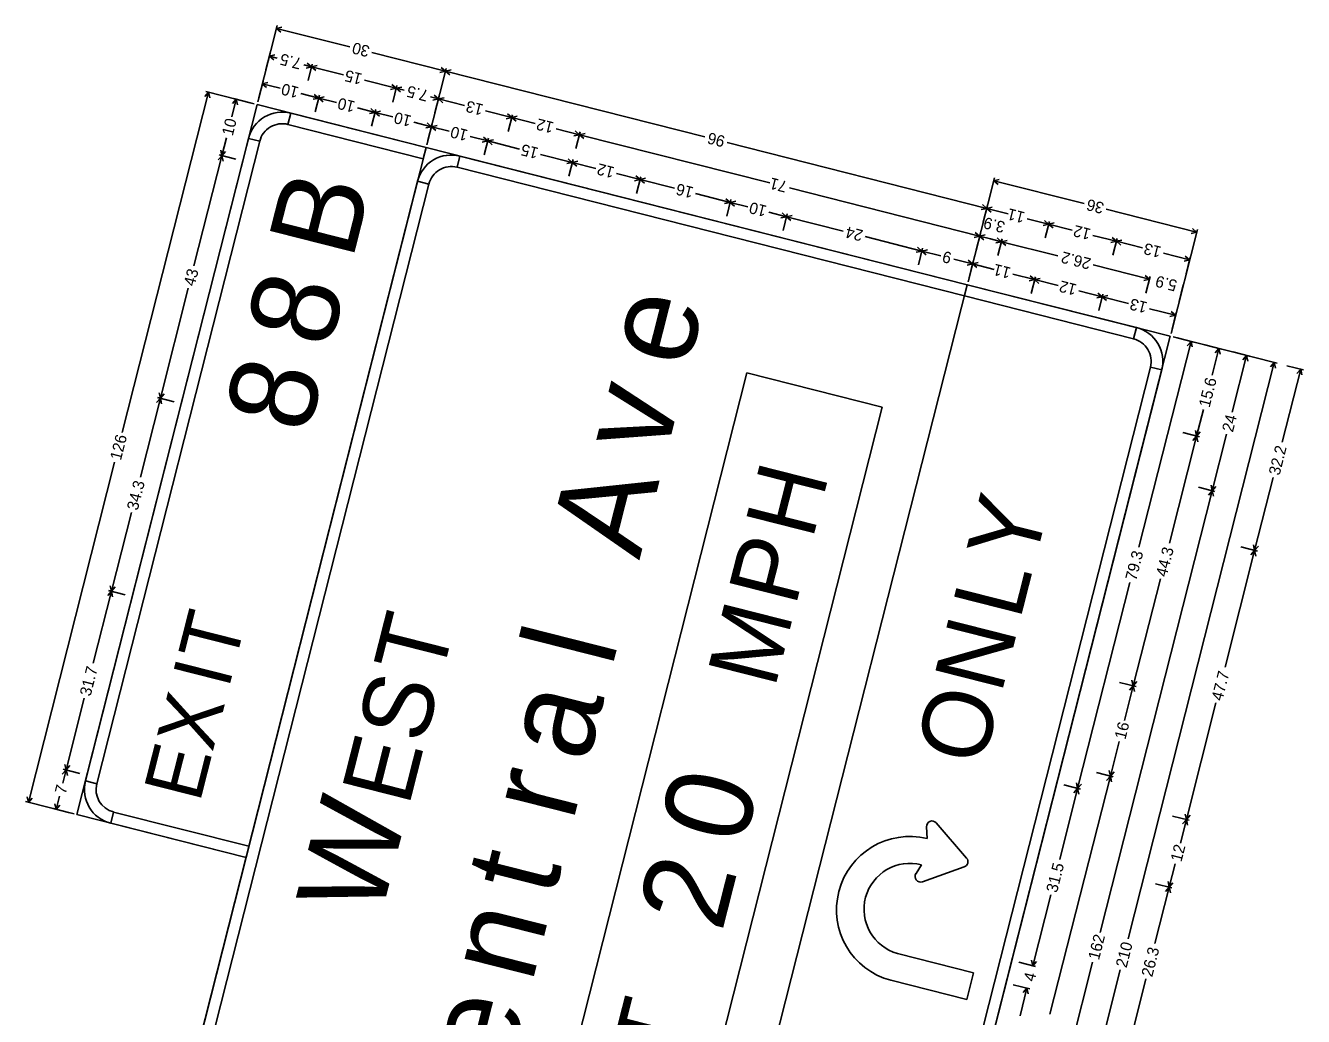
# Model space of a CAD drawing. Extents: x 670003 to 670131, y 737764 to 738002.
# Drawn here: x 670009.58 to 670027.92, y 737772.13 to 737786.35 of the extents above; entities that cross this region are included whole.
import ezdxf

# ---------------------------------------------------------------- set-up
doc = ezdxf.new("R2010")
doc.units = 0
doc.layers.add('R_SIGN', color=7, linetype='Continuous')

msp = doc.modelspace()

# ---------------------------------------------------------------- linework, layer by layer
at = {"layer": 'R_SIGN'}
for p, q in [((670013.193, 737786.345), (670012.915, 737785.251)), ((670013.263, 737786.323), (670013.183, 737786.305)), ((670014.238, 737786.038), (670013.183, 737786.305)), ((670013.245, 737786.252), (670013.183, 737786.305)), ((670013.092, 737785.947), (670013.031, 737785.708)), ((670013.162, 737785.925), (670013.082, 737785.907)), ((670013.195, 737785.879), (670013.082, 737785.907)), ((670013.144, 737785.854), (670013.082, 737785.907)), ((670014.553, 737785.958), (670015.609, 737785.69)), ((670013.575, 737785.782), (670013.688, 737785.754)), ((670013.608, 737785.736), (670013.688, 737785.754)), ((670013.626, 737785.807), (670013.688, 737785.754)), ((670013.698, 737785.793), (670013.638, 737785.555)), ((670013.768, 737785.771), (670013.688, 737785.754)), ((670014.144, 737785.638), (670013.688, 737785.754)), ((670013.75, 737785.7), (670013.688, 737785.754)), ((670015.619, 737785.73), (670015.341, 737784.635)), ((670015.619, 737785.73), (670015.341, 737784.635)), ((670015.528, 737785.672), (670015.609, 737785.69)), ((670015.547, 737785.744), (670015.609, 737785.69)), ((670015.689, 737785.708), (670015.609, 737785.69)), ((670019.331, 737784.746), (670015.609, 737785.69)), ((670015.671, 737785.636), (670015.609, 737785.69)), ((670012.991, 737785.549), (670012.93, 737785.31)), ((670013.061, 737785.527), (670012.981, 737785.509)), ((670013.235, 737785.445), (670012.981, 737785.509)), ((670013.043, 737785.456), (670012.981, 737785.509)), ((670014.445, 737785.562), (670014.901, 737785.446)), ((670014.839, 737785.5), (670014.901, 737785.446)), ((670010.971, 737780.508), (670012.209, 737785.388)), ((670012.155, 737785.325), (670012.209, 737785.388)), ((670012.169, 737785.398), (670012.865, 737785.221)), ((670012.226, 737785.307), (670012.209, 737785.388)), ((670013.535, 737785.369), (670013.79, 737785.304)), ((670013.727, 737785.358), (670013.79, 737785.304)), ((670013.8, 737785.344), (670013.739, 737785.105)), ((670013.87, 737785.322), (670013.79, 737785.304)), ((670014.821, 737785.428), (670014.901, 737785.446)), ((670014.911, 737785.486), (670014.851, 737785.247)), ((670014.911, 737785.486), (670014.851, 737785.247)), ((670014.981, 737785.463), (670014.901, 737785.446)), ((670015.015, 737785.417), (670014.901, 737785.446)), ((670014.963, 737785.392), (670014.901, 737785.446)), ((670015.394, 737785.321), (670015.508, 737785.292)), ((670015.446, 737785.346), (670015.508, 737785.292)), ((670015.518, 737785.332), (670015.457, 737785.093)), ((670015.518, 737785.332), (670015.457, 737785.093)), ((670015.588, 737785.31), (670015.508, 737785.292)), ((670012.905, 737785.211), (670010.321, 737775.022)), ((670012.542, 737785.033), (670012.607, 737785.287)), ((670012.553, 737785.225), (670012.607, 737785.287)), ((670012.567, 737785.297), (670012.806, 737785.236)), ((670012.624, 737785.206), (670012.607, 737785.287)), ((670015.331, 737784.596), (670012.905, 737785.211)), ((670013.709, 737785.287), (670013.79, 737785.304)), ((670014.044, 737785.24), (670013.79, 737785.304)), ((670013.852, 737785.251), (670013.79, 737785.304)), ((670014.344, 737785.164), (670014.598, 737785.099)), ((670014.536, 737785.153), (670014.598, 737785.099)), ((670014.608, 737785.139), (670014.548, 737784.9)), ((670014.608, 737785.139), (670014.548, 737784.9)), ((670015.428, 737785.275), (670015.508, 737785.292)), ((670015.883, 737785.197), (670015.508, 737785.292)), ((670015.57, 737785.238), (670015.508, 737785.292)), ((670013.349, 737784.926), (670013.39, 737785.088)), ((670014.518, 737785.082), (670014.598, 737785.099)), ((670014.678, 737785.117), (670014.598, 737785.099)), ((670014.852, 737785.035), (670014.598, 737785.099)), ((670014.66, 737785.046), (670014.598, 737785.099)), ((670015.153, 737784.959), (670015.407, 737784.894)), ((670015.345, 737784.948), (670015.407, 737784.894)), ((670016.184, 737785.121), (670016.559, 737785.025)), ((670016.479, 737785.008), (670016.559, 737785.025)), ((670016.497, 737785.079), (670016.559, 737785.025)), ((670016.569, 737785.065), (670016.509, 737784.827)), ((670016.639, 737785.043), (670016.559, 737785.025)), ((670016.894, 737784.94), (670016.559, 737785.025)), ((670016.621, 737784.972), (670016.559, 737785.025)), ((670015.327, 737784.877), (670015.407, 737784.894)), ((670015.417, 737784.934), (670015.356, 737784.695)), ((670015.417, 737784.934), (670015.356, 737784.695)), ((670015.487, 737784.912), (670015.407, 737784.894)), ((670015.661, 737784.83), (670015.407, 737784.894)), ((670015.469, 737784.84), (670015.407, 737784.894)), ((670017.194, 737784.864), (670017.529, 737784.779)), ((670017.449, 737784.762), (670017.529, 737784.779)), ((670017.467, 737784.833), (670017.529, 737784.779)), ((670017.54, 737784.819), (670017.479, 737784.58)), ((670017.54, 737784.819), (670017.479, 737784.58)), ((670017.61, 737784.797), (670017.529, 737784.779)), ((670020.259, 737784.087), (670017.529, 737784.779)), ((670017.592, 737784.726), (670017.529, 737784.779)), ((670015.331, 737784.596), (670011.024, 737767.614)), ((670012.466, 737784.732), (670012.402, 737784.478)), ((670012.747, 737774.406), (670015.331, 737784.596)), ((670012.782, 737784.726), (670012.944, 737784.685)), ((670023.094, 737782.627), (670015.331, 737784.596)), ((670015.961, 737784.753), (670016.215, 737784.689)), ((670016.135, 737784.672), (670016.215, 737784.689)), ((670016.153, 737784.743), (670016.215, 737784.689)), ((670016.226, 737784.729), (670016.165, 737784.49)), ((670016.296, 737784.707), (670016.215, 737784.689)), ((670016.671, 737784.573), (670016.215, 737784.689)), ((670016.278, 737784.635), (670016.215, 737784.689)), ((670019.649, 737784.665), (670023.372, 737783.721)), ((670012.001, 737782.899), (670012.402, 737784.478)), ((670012.348, 737784.416), (670012.402, 737784.478)), ((670012.362, 737784.488), (670012.601, 737784.428)), ((670012.362, 737784.488), (670012.601, 737784.428)), ((670012.384, 737784.558), (670012.402, 737784.478)), ((670012.455, 737784.54), (670012.402, 737784.478)), ((670012.419, 737784.398), (670012.402, 737784.478)), ((670015.775, 737784.311), (670015.816, 737784.473)), ((670016.973, 737784.497), (670017.428, 737784.381)), ((670017.366, 737784.435), (670017.428, 737784.381)), ((670017.439, 737784.421), (670017.378, 737784.182)), ((670017.509, 737784.399), (670017.428, 737784.381)), ((670017.348, 737784.364), (670017.428, 737784.381)), ((670017.764, 737784.296), (670017.428, 737784.381)), ((670017.491, 737784.328), (670017.428, 737784.381)), ((670018.064, 737784.22), (670018.399, 737784.135)), ((670015.208, 737784.11), (670015.37, 737784.069)), ((670018.319, 737784.118), (670018.399, 737784.135)), ((670018.337, 737784.189), (670018.399, 737784.135)), ((670018.409, 737784.175), (670018.348, 737783.936)), ((670018.479, 737784.153), (670018.399, 737784.135)), ((670018.894, 737784.01), (670018.399, 737784.135)), ((670018.461, 737784.082), (670018.399, 737784.135)), ((670023.483, 737784.159), (670023.104, 737782.667)), ((670023.553, 737784.137), (670023.473, 737784.119)), ((670024.77, 737783.79), (670023.473, 737784.119)), ((670023.535, 737784.065), (670023.473, 737784.119)), ((670019.197, 737783.933), (670019.693, 737783.807)), ((670019.631, 737783.861), (670019.693, 737783.807)), ((670019.703, 737783.847), (670019.642, 737783.608)), ((670020.542, 737784.015), (670023.271, 737783.323)), ((670019.613, 737783.79), (670019.693, 737783.807)), ((670019.773, 737783.825), (670019.693, 737783.807)), ((670019.947, 737783.743), (670019.693, 737783.807)), ((670019.755, 737783.753), (670019.693, 737783.807)), ((670020.247, 737783.666), (670020.501, 737783.602)), ((670023.382, 737783.761), (670023.104, 737782.667)), ((670023.292, 737783.704), (670023.372, 737783.721)), ((670023.31, 737783.775), (670023.372, 737783.721)), ((670023.382, 737783.761), (670023.321, 737783.522)), ((670023.452, 737783.739), (670023.372, 737783.721)), ((670023.682, 737783.642), (670023.372, 737783.721)), ((670023.434, 737783.667), (670023.372, 737783.721)), ((670025.087, 737783.71), (670026.384, 737783.381)), ((670020.421, 737783.584), (670020.501, 737783.602)), ((670020.439, 737783.656), (670020.501, 737783.602)), ((670020.511, 737783.642), (670020.451, 737783.403)), ((670020.582, 737783.62), (670020.501, 737783.602)), ((670021.313, 737783.396), (670020.501, 737783.602)), ((670020.564, 737783.548), (670020.501, 737783.602)), ((670023.951, 737783.574), (670024.261, 737783.495)), ((670024.181, 737783.478), (670024.261, 737783.495)), ((670024.199, 737783.549), (670024.261, 737783.495)), ((670024.271, 737783.535), (670024.211, 737783.297)), ((670024.342, 737783.513), (670024.261, 737783.495)), ((670024.597, 737783.41), (670024.261, 737783.495)), ((670024.324, 737783.442), (670024.261, 737783.495)), ((670021.63, 737783.316), (670022.442, 737783.11)), ((670023.191, 737783.306), (670023.271, 737783.323)), ((670023.209, 737783.377), (670023.271, 737783.323)), ((670023.281, 737783.363), (670023.22, 737783.124)), ((670023.281, 737783.363), (670023.22, 737783.124)), ((670023.351, 737783.341), (670023.271, 737783.323)), ((670023.428, 737783.283), (670023.271, 737783.323)), ((670023.333, 737783.27), (670023.271, 737783.323)), ((670023.522, 737783.297), (670023.584, 737783.244)), ((670024.896, 737783.334), (670025.232, 737783.249)), ((670025.17, 737783.303), (670025.232, 737783.249)), ((670026.394, 737783.421), (670026.016, 737781.928)), ((670026.304, 737783.363), (670026.384, 737783.381)), ((670026.322, 737783.434), (670026.384, 737783.381)), ((670022.362, 737783.092), (670022.442, 737783.11)), ((670022.38, 737783.163), (670022.442, 737783.11)), ((670022.452, 737783.15), (670022.392, 737782.911)), ((670022.452, 737783.15), (670022.392, 737782.911)), ((670022.522, 737783.127), (670022.442, 737783.11)), ((670022.712, 737783.041), (670022.442, 737783.11)), ((670022.504, 737783.056), (670022.442, 737783.11)), ((670023.428, 737783.283), (670023.584, 737783.244)), ((670023.504, 737783.226), (670023.584, 737783.244)), ((670023.594, 737783.283), (670023.534, 737783.045)), ((670023.664, 737783.261), (670023.584, 737783.244)), ((670024.391, 737783.039), (670023.584, 737783.244)), ((670023.646, 737783.19), (670023.584, 737783.244)), ((670025.152, 737783.232), (670025.232, 737783.249)), ((670025.242, 737783.289), (670025.181, 737783.05)), ((670025.242, 737783.289), (670025.181, 737783.05)), ((670025.312, 737783.267), (670025.232, 737783.249)), ((670025.607, 737783.154), (670025.232, 737783.249)), ((670025.294, 737783.196), (670025.232, 737783.249)), ((670022.9, 737782.994), (670023.17, 737782.925)), ((670023.09, 737782.908), (670023.17, 737782.925)), ((670023.108, 737782.979), (670023.17, 737782.925)), ((670023.18, 737782.965), (670023.12, 737782.726)), ((670023.18, 737782.965), (670023.12, 737782.726)), ((670023.25, 737782.943), (670023.17, 737782.925)), ((670023.48, 737782.846), (670023.17, 737782.925)), ((670023.232, 737782.872), (670023.17, 737782.925)), ((670025.908, 737783.078), (670026.283, 737782.983)), ((670026.203, 737782.965), (670026.283, 737782.983)), ((670026.221, 737783.036), (670026.283, 737782.983)), ((670026.293, 737783.023), (670026.233, 737782.784)), ((670023.749, 737782.778), (670024.06, 737782.7)), ((670023.997, 737782.753), (670024.06, 737782.7)), ((670024.9, 737782.91), (670025.707, 737782.705)), ((670025.645, 737782.759), (670025.707, 737782.705)), ((670025.717, 737782.745), (670025.657, 737782.506)), ((670025.717, 737782.745), (670025.657, 737782.506)), ((670011.919, 737782.576), (670011.519, 737780.997)), ((670018.787, 737765.645), (670023.094, 737782.627)), ((670023.094, 737782.627), (670018.787, 737765.645)), ((670026.005, 737781.888), (670023.094, 737782.627)), ((670023.979, 737782.682), (670024.06, 737782.7)), ((670024.07, 737782.739), (670024.009, 737782.501)), ((670024.14, 737782.717), (670024.06, 737782.7)), ((670024.395, 737782.615), (670024.06, 737782.7)), ((670024.122, 737782.646), (670024.06, 737782.7)), ((670025.627, 737782.688), (670025.707, 737782.705)), ((670026.192, 737782.625), (670026.132, 737782.386)), ((670024.695, 737782.539), (670025.03, 737782.453)), ((670024.95, 737782.436), (670025.03, 737782.453)), ((670024.968, 737782.507), (670025.03, 737782.453)), ((670025.04, 737782.493), (670024.979, 737782.254)), ((670025.04, 737782.493), (670024.979, 737782.254)), ((670025.11, 737782.471), (670025.03, 737782.453)), ((670025.405, 737782.358), (670025.03, 737782.453)), ((670025.092, 737782.4), (670025.03, 737782.453)), ((670025.706, 737782.282), (670026.081, 737782.187)), ((670026.019, 737782.24), (670026.081, 737782.187)), ((670026.091, 737782.227), (670026.031, 737781.988)), ((670025.52, 737782.011), (670025.479, 737781.85)), ((670026.001, 737782.169), (670026.081, 737782.187)), ((670021.698, 737764.906), (670026.005, 737781.888)), ((670027.538, 737781.5), (670026.045, 737781.878)), ((670026.344, 737781.803), (670026.105, 737781.863)), ((670025.555, 737778.859), (670026.304, 737781.813)), ((670026.25, 737781.751), (670026.304, 737781.813)), ((670026.321, 737781.733), (670026.304, 737781.813)), ((670026.742, 737781.702), (670026.503, 737781.762)), ((670026.605, 737781.33), (670026.702, 737781.712)), ((670026.648, 737781.65), (670026.702, 737781.712)), ((670026.719, 737781.632), (670026.702, 737781.712)), ((670027.14, 737781.601), (670026.901, 737781.661)), ((670025.401, 737773.242), (670027.498, 737781.51)), ((670026.894, 737780.799), (670027.1, 737781.611)), ((670027.046, 737781.549), (670027.1, 737781.611)), ((670027.117, 737781.531), (670027.1, 737781.611)), ((670027.444, 737781.448), (670027.498, 737781.51)), ((670027.515, 737781.43), (670027.498, 737781.51)), ((670027.916, 737781.404), (670027.677, 737781.464)), ((670016.611, 737768.262), (670019.933, 737781.363)), ((670019.933, 737781.363), (670021.874, 737780.871)), ((670025.721, 737781.444), (670025.882, 737781.403)), ((670027.61, 737780.366), (670027.876, 737781.414)), ((670027.822, 737781.352), (670027.876, 737781.414)), ((670027.893, 737781.334), (670027.876, 737781.414)), ((670011.232, 737779.865), (670011.519, 737780.997)), ((670011.465, 737780.935), (670011.519, 737780.997)), ((670011.479, 737781.007), (670011.718, 737780.946)), ((670011.501, 737781.077), (670011.519, 737780.997)), ((670011.572, 737781.059), (670011.519, 737780.997)), ((670011.536, 737780.916), (670011.519, 737780.997)), ((670021.874, 737780.871), (670018.552, 737767.77)), ((670026.48, 737780.835), (670026.383, 737780.453)), ((670025.994, 737778.919), (670026.383, 737780.453)), ((670026.423, 737780.443), (670026.184, 737780.504)), ((670026.423, 737780.443), (670026.184, 737780.504)), ((670026.329, 737780.391), (670026.383, 737780.453)), ((670026.365, 737780.534), (670026.383, 737780.453)), ((670026.436, 737780.516), (670026.383, 737780.453)), ((670026.4, 737780.373), (670026.383, 737780.453)), ((670026.814, 737780.482), (670026.608, 737779.67)), ((670010.862, 737780.078), (670009.625, 737775.198)), ((670027.482, 737779.861), (670027.216, 737778.813)), ((670025.001, 737773.333), (670026.608, 737779.67)), ((670026.647, 737779.66), (670026.409, 737779.72)), ((670026.647, 737779.66), (670026.409, 737779.72)), ((670026.554, 737779.608), (670026.608, 737779.67)), ((670026.59, 737779.75), (670026.608, 737779.67)), ((670026.661, 737779.732), (670026.608, 737779.67)), ((670026.625, 737779.59), (670026.608, 737779.67)), ((670011.103, 737779.358), (670010.816, 737778.227)), ((670027.199, 737778.893), (670027.216, 737778.813)), ((670026.792, 737777.139), (670027.216, 737778.813)), ((670027.256, 737778.803), (670027.017, 737778.863)), ((670027.256, 737778.803), (670027.017, 737778.863)), ((670027.163, 737778.751), (670027.216, 737778.813)), ((670027.27, 737778.875), (670027.216, 737778.813)), ((670027.234, 737778.733), (670027.216, 737778.813)), ((670025.426, 737778.352), (670024.677, 737775.398)), ((670025.863, 737778.404), (670025.474, 737776.869)), ((670010.555, 737777.198), (670010.816, 737778.227)), ((670010.763, 737778.165), (670010.816, 737778.227)), ((670010.776, 737778.237), (670011.015, 737778.177)), ((670010.799, 737778.307), (670010.816, 737778.227)), ((670010.87, 737778.289), (670010.816, 737778.227)), ((670010.834, 737778.147), (670010.816, 737778.227)), ((670025.514, 737776.859), (670025.275, 737776.92)), ((670025.456, 737776.95), (670025.474, 737776.869)), ((670025.527, 737776.932), (670025.474, 737776.869)), ((670010.427, 737776.692), (670010.166, 737775.664)), ((670025.348, 737776.374), (670025.474, 737776.869)), ((670025.42, 737776.807), (670025.474, 737776.869)), ((670025.491, 737776.789), (670025.474, 737776.869)), ((670026.661, 737776.625), (670026.237, 737774.951)), ((670025.271, 737776.071), (670025.146, 737775.576)), ((670010.112, 737775.601), (670010.166, 737775.664)), ((670010.118, 737775.474), (670010.166, 737775.664)), ((670010.126, 737775.674), (670010.365, 737775.613)), ((670010.148, 737775.744), (670010.166, 737775.664)), ((670010.22, 737775.726), (670010.166, 737775.664)), ((670010.184, 737775.583), (670010.166, 737775.664)), ((670025.185, 737775.566), (670024.947, 737775.626)), ((670025.128, 737775.656), (670025.146, 737775.576)), ((670025.199, 737775.638), (670025.146, 737775.576)), ((670010.606, 737775.466), (670010.444, 737775.507)), ((670024.28, 737772.161), (670025.146, 737775.576)), ((670024.717, 737775.387), (670024.478, 737775.448)), ((670024.717, 737775.387), (670024.478, 737775.448)), ((670024.659, 737775.478), (670024.677, 737775.398)), ((670024.731, 737775.46), (670024.677, 737775.398)), ((670025.092, 737775.513), (670025.146, 737775.576)), ((670025.163, 737775.495), (670025.146, 737775.576)), ((670009.607, 737775.279), (670009.625, 737775.198)), ((670009.678, 737775.261), (670009.625, 737775.198)), ((670010.071, 737775.287), (670010.022, 737775.097)), ((670024.419, 737774.38), (670024.677, 737775.398)), ((670024.623, 737775.335), (670024.677, 737775.398)), ((670024.694, 737775.317), (670024.677, 737775.398)), ((670009.585, 737775.209), (670010.281, 737775.032)), ((670009.983, 737775.108), (670010.221, 737775.047)), ((670010.005, 737775.178), (670010.022, 737775.097)), ((670010.076, 737775.16), (670010.022, 737775.097)), ((670010.806, 737774.899), (670010.847, 737775.06)), ((670010.321, 737775.022), (670012.747, 737774.406)), ((670023.084, 737774.398), (670022.647, 737774.905)), ((670026.277, 737774.941), (670026.038, 737775.001)), ((670026.152, 737774.615), (670026.237, 737774.951)), ((670026.183, 737774.889), (670026.237, 737774.951)), ((670026.219, 737775.031), (670026.237, 737774.951)), ((670026.29, 737775.013), (670026.237, 737774.951)), ((670026.254, 737774.871), (670026.237, 737774.951)), ((670022.519, 737774.679), (670022.509, 737774.849)), ((670012.747, 737774.406), (670012.747, 737774.406)), ((670026.076, 737774.316), (670025.991, 737773.98)), ((670022.437, 737774.301), (670022.358, 737774.176)), ((670023.051, 737774.272), (670022.45, 737774.06)), ((670025.786, 737773.174), (670025.991, 737773.98)), ((670026.03, 737773.97), (670025.792, 737774.031)), ((670025.937, 737773.918), (670025.991, 737773.98)), ((670025.973, 737774.061), (670025.991, 737773.98)), ((670026.044, 737774.043), (670025.991, 737773.98)), ((670026.008, 737773.9), (670025.991, 737773.98)), ((670024.29, 737773.873), (670024.032, 737772.855)), ((670023.183, 737772.753), (670022.093, 737773.03)), ((670024.892, 737772.906), (670023.285, 737766.57)), ((670024.072, 737772.845), (670023.833, 737772.906)), ((670024.015, 737772.935), (670024.032, 737772.855)), ((670024.086, 737772.917), (670024.032, 737772.855)), ((670023.085, 737772.368), (670023.183, 737772.753)), ((670025.288, 737772.796), (670023.191, 737764.528)), ((670025.657, 737772.664), (670025.452, 737771.858)), ((670023.085, 737772.368), (670021.996, 737772.645)), ((670023.99, 737772.522), (670023.751, 737772.582)), ((670023.85, 737772.135), (670023.95, 737772.532)), ((670023.896, 737772.47), (670023.95, 737772.532)), ((670023.968, 737772.451), (670023.95, 737772.532))]:
    msp.add_line(p, q, dxfattribs=at)
for points in [[(670015.29, 737784.434), (670013.349, 737784.926), (670013.39, 737785.088), (670015.331, 737784.596), (670015.29, 737784.434)], [(670012.944, 737784.685), (670010.606, 737775.466), (670010.444, 737775.507), (670012.782, 737784.726), (670012.944, 737784.685)], [(670023.053, 737782.465), (670015.775, 737784.311), (670015.816, 737784.473), (670023.094, 737782.627), (670023.053, 737782.465)], [(670015.37, 737784.069), (670011.309, 737768.058), (670011.147, 737768.099), (670015.208, 737784.11), (670015.37, 737784.069)], [(670025.479, 737781.85), (670023.053, 737782.465), (670023.094, 737782.627), (670025.52, 737782.011), (670025.479, 737781.85)], [(670021.66, 737765.433), (670025.721, 737781.444), (670025.882, 737781.403), (670021.822, 737765.392), (670021.66, 737765.433)], [(670010.847, 737775.06), (670012.788, 737774.568), (670012.747, 737774.406), (670010.806, 737774.899), (670010.847, 737775.06)]]:
    msp.add_lwpolyline(points, close=True, dxfattribs=at)
for centre, radius, start, end in [((670013.267, 737784.603), 0.501, 75.7686, 165.7688), ((670013.267, 737784.603), 0.334, 75.7686, 165.7688), ((670015.693, 737783.987), 0.501, 75.7686, 165.7688), ((670015.693, 737783.987), 0.334, 75.7686, 165.7688), ((670025.397, 737781.526), 0.501, 345.7686, 75.7688), ((670025.397, 737781.526), 0.334, 345.7686, 75.7688), ((670010.929, 737775.384), 0.501, 165.7688, 255.7684), ((670010.929, 737775.384), 0.334, 165.7688, 255.7684), ((670022.588, 737774.853), 0.0785, 40.7767, 183.2283), ((670022.268, 737773.659), 1.05, 76.1684, 254.9793), ((670022.271, 737773.664), 0.659, 75.3868, 254.3334), ((670023.025, 737774.346), 0.0785, 289.4736, 40.7767), ((670022.424, 737774.134), 0.0785, 147.5362, 289.4736)]:
    msp.add_arc(centre, radius, start, end, dxfattribs=at)

# ---------------------------------------------------------------- texts
for s, height, rotation, p in [('30', 0.1642, 165.7688, (670014.533, 737786.048)), ('7.5', 0.1642, 165.7688, (670013.555, 737785.872)), ('15', 0.1642, 165.7688, (670014.426, 737785.651)), ('10', 0.1642, 165.7688, (670013.516, 737785.458)), ('7.5', 0.1642, 165.7688, (670015.375, 737785.411)), ('10', 0.1642, 165.7688, (670014.324, 737785.253)), ('13', 0.1642, 165.7688, (670016.164, 737785.21)), ('10', 0.1642, 75.7686, (670012.556, 737784.752)), ('10', 0.1642, 165.7688, (670015.133, 737785.048)), ('12', 0.1642, 165.7688, (670017.174, 737784.954)), ('10', 0.1642, 165.7688, (670015.942, 737784.843)), ('96', 0.1642, 165.7688, (670019.63, 737784.755)), ('15', 0.1642, 165.7688, (670016.953, 737784.587)), ('12', 0.1642, 165.7688, (670018.044, 737784.31)), ('B', 1.251, 75.7686, (670014.27, 737782.958)), ('16', 0.1642, 165.7688, (670019.178, 737784.022)), ('71', 0.1642, 165.7688, (670020.522, 737784.105)), ('36', 0.1642, 165.7688, (670025.067, 737783.799)), ('10', 0.1642, 165.7688, (670020.228, 737783.756)), ('11', 0.1642, 165.7688, (670023.931, 737783.664)), ('3.9', 0.1642, 165.7688, (670023.648, 737783.524)), ('12', 0.1642, 165.7688, (670024.877, 737783.424)), ('24', 0.1642, 165.7688, (670021.611, 737783.405)), ('13', 0.1642, 165.7688, (670025.888, 737783.168)), ('9', 0.164, 165.7688, (670022.881, 737783.083)), ('11', 0.1642, 165.7688, (670023.73, 737782.868)), ('26.2', 0.1642, 165.7688, (670024.88, 737783)), ('43', 0.1642, 75.7686, (670012.009, 737782.595)), ('8', 1.251, 75.7686, (670013.947, 737781.685)), ('5.9', 0.1642, 165.7688, (670026.115, 737782.686)), ('12', 0.1642, 165.7688, (670024.675, 737782.628)), ('e', 1.335, 75.7686, (670019.081, 737781.396)), ('13', 0.1642, 165.7688, (670025.687, 737782.372)), ('8', 1.251, 75.7686, (670013.637, 737780.46)), ('15.6', 0.1642, 75.7686, (670026.569, 737780.855)), ('v', 1.335, 75.7686, (670018.763, 737780.141)), ('24', 0.1642, 75.7686, (670026.903, 737780.501)), ('126', 0.1642, 75.7686, (670010.952, 737780.097)), ('32.2', 0.1642, 75.7686, (670027.572, 737779.88)), ('H', 1.001, 75.7686, (670020.872, 737778.953)), ('34.3', 0.1642, 75.7686, (670011.193, 737779.378)), ('A', 1.335, 75.7686, (670018.389, 737778.666)), ('Y', 1.001, 75.7686, (670024.046, 737778.574)), ('P', 1.001, 75.7686, (670020.628, 737777.993)), ('79.3', 0.1642, 75.7686, (670025.516, 737778.371)), ('44.3', 0.1642, 75.7686, (670025.953, 737778.424)), ('L', 1.001, 75.7686, (670023.849, 737777.798)), ('T', 0.834, 75.7686, (670012.58, 737777.143)), ('M', 1.001, 75.7686, (670020.33, 737776.818)), ('T', 1.001, 75.7686, (670015.544, 737776.95)), ('N', 1.001, 75.7686, (670023.581, 737776.74)), ('l', 1.335, 75.7686, (670017.995, 737777.114)), ('31.7', 0.1642, 75.7686, (670010.517, 737776.712)), ('I', 0.834, 75.7686, (670012.496, 737776.811)), ('47.7', 0.1642, 75.7686, (670026.751, 737776.645)), ('S', 1.001, 75.7686, (670015.307, 737776.018)), ('X', 0.834, 75.7686, (670012.267, 737775.909)), ('a', 1.335, 75.7686, (670017.647, 737775.742)), ('O', 1.001, 75.7686, (670023.315, 737775.692)), ('16', 0.1642, 75.7686, (670025.361, 737776.091)), ('E', 1.001, 75.7686, (670015.081, 737775.125)), ('E', 0.834, 75.7686, (670012.082, 737775.178)), ('r', 1.335, 75.7686, (670017.434, 737774.901)), ('0', 1.251, 75.7686, (670019.885, 737774.556)), ('7', 0.164, 75.7686, (670010.16, 737775.307)), ('W', 1.251, 75.7686, (670014.673, 737773.516)), ('t', 1.335, 75.7686, (670017.158, 737773.814)), ('12', 0.1642, 75.7686, (670026.165, 737774.335)), ('2', 1.251, 75.7686, (670019.572, 737773.319)), ('31.5', 0.1642, 75.7686, (670024.38, 737773.892)), ('n', 1.335, 75.7686, (670016.847, 737772.585)), ('162', 0.1642, 75.7686, (670024.982, 737772.926)), ('210', 0.1642, 75.7686, (670025.378, 737772.816)), ('26.3', 0.1642, 75.7686, (670025.746, 737772.683)), ('4', 0.164, 75.7686, (670024.056, 737772.616)), ('e', 1.335, 75.7686, (670016.528, 737771.33)), ('T', 1.001, 75.7686, (670018.961, 737771.418))]:
    msp.add_text(s, height=height, rotation=rotation, dxfattribs=at).set_placement(p)

doc.saveas('drawing.dxf')
